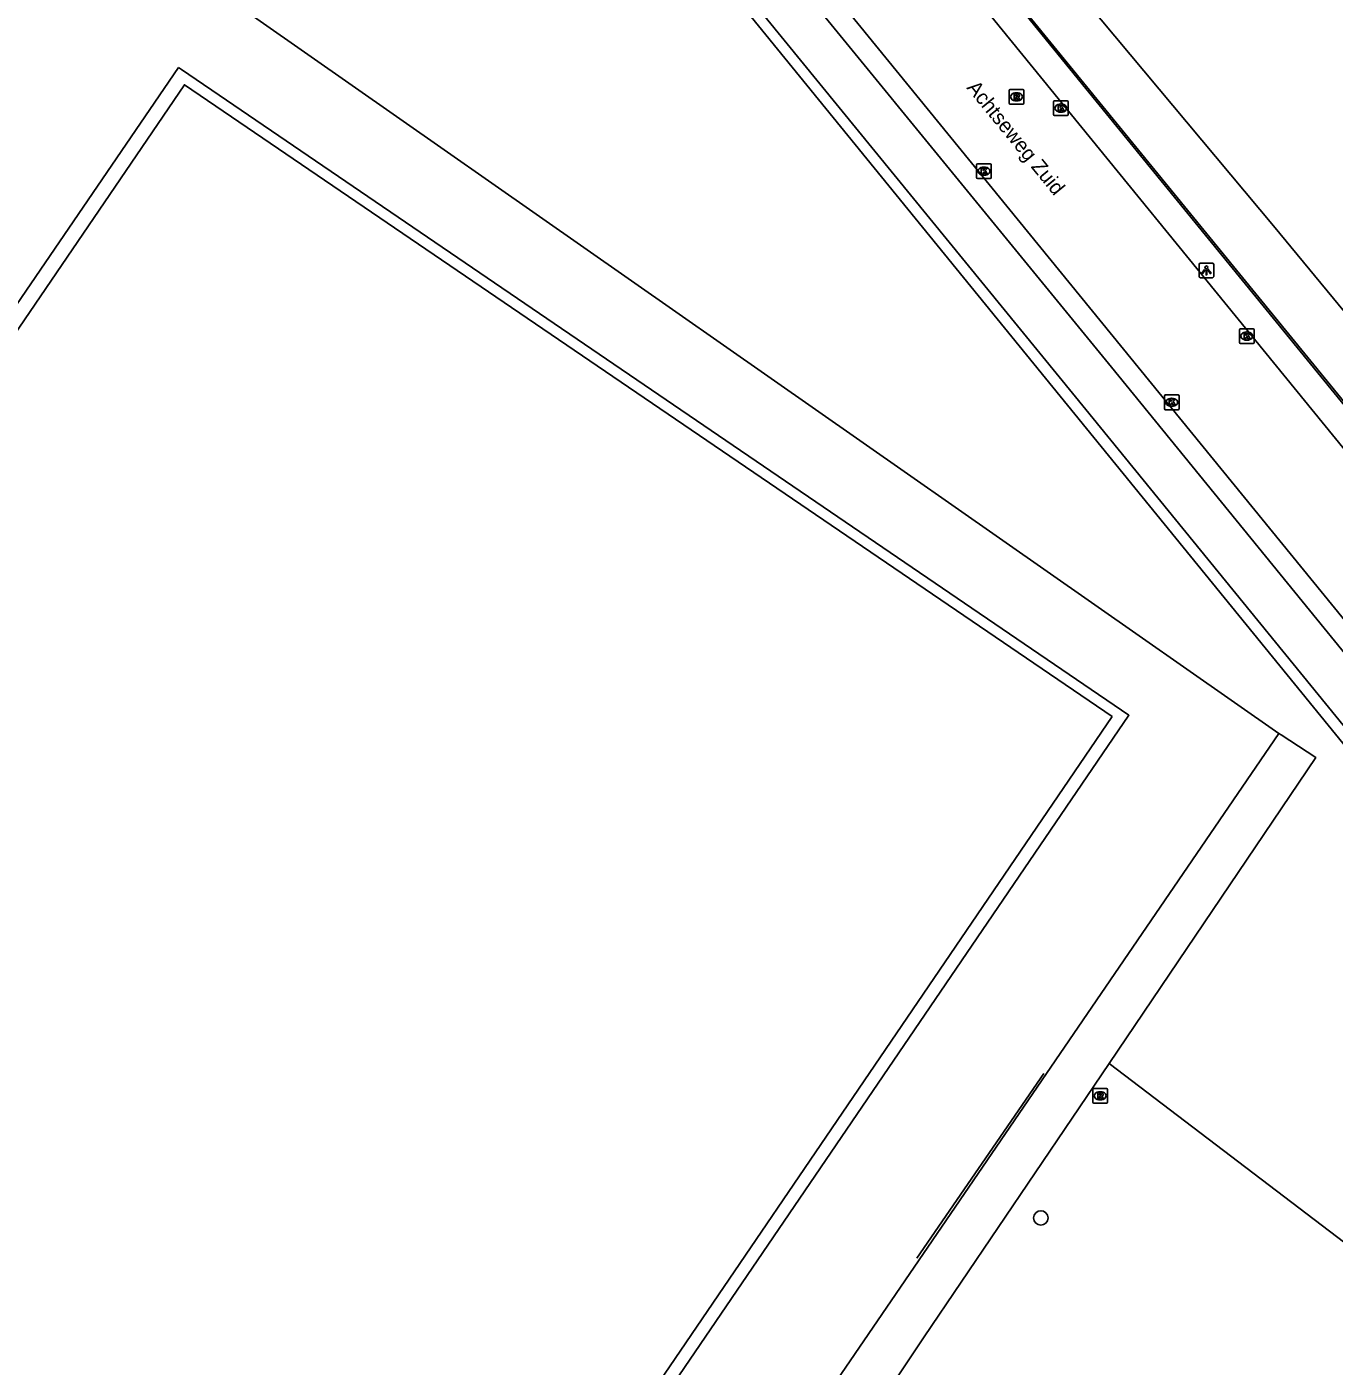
# Model space of a CAD drawing. Extents: x 157154 to 159278, y 385000 to 386650.
# Drawn here: x 158667 to 158755.9, y 385821 to 385911.9 of the extents above; entities that cross this region are included whole.
import ezdxf

# ---------------------------------------------------------------- set-up
doc = ezdxf.new("R2010")
doc.units = 0
for name, color, linetype in [('IMGEO_Berm_groen', 7, 'Continuous'), ('IMGEO_Boom', 7, 'Continuous'), ('IMGEO_Fietspad_gesloten', 7, 'Continuous'), ('IMGEO_Gemengd_bos', 7, 'Continuous'), ('IMGEO_Groenvoorziening', 7, 'Continuous'), ('IMGEO_Hek', 7, 'Continuous'), ('IMGEO_Kolk', 7, 'Continuous'), ('IMGEO_Lichtpunt', 7, 'Continuous'), ('IMGEO_Openbare_ruimte_label', 7, 'Continuous'), ('IMGEO_Rijbaan_lokaal_open', 7, 'Continuous'), ('IMGEO_Rioolput', 7, 'Continuous'), ('IMGEO_Spoorbaan_halfverhard', 7, 'Continuous'), ('IMGEO_Voetpad_open', 7, 'Continuous')]:
    doc.layers.add(name, color=color, linetype=linetype)

msp = doc.modelspace()

# ---------------------------------------------------------------- linework, layer by layer
at = {"layer": 'IMGEO_Berm_groen'}
msp.add_lwpolyline([(158841.489, 385782.337), (158835.15, 385790.114), (158809.757, 385821.269), (158676.254, 385984.739), (158663.791, 386000), (158641.091, 386027.796), (158568.335, 386116.93)], dxfattribs=at)
at = {"layer": 'IMGEO_Boom'}
msp.add_circle((158735.924, 385831.028), 0.489, dxfattribs=at)
at = {"layer": 'IMGEO_Fietspad_gesloten'}
for points in [[(158496.283, 386187.658), (158499.727, 386183.447), (158522.187, 386156.142), (158552.142, 386119.431), (158582.074, 386082.79), (158611.265, 386046.941), (158624.352, 386030.949), (158632.65, 386020.898), (158649.904, 386000), (158653.358, 385995.817), (158682.792, 385959.807), (158711.087, 385925.065), (158740.719, 385888.815), (158770.311, 385852.497), (158799.749, 385816.443), (158822.714, 385788.211), (158826.18, 385783.962)], [(158827.277, 385777.76), (158822.455, 385783.643), (158820.309, 385786.377), (158797.347, 385814.415), (158767.845, 385850.525), (158738.269, 385886.799), (158708.596, 385923.166), (158680.309, 385957.863), (158650.869, 385993.846), (158645.822, 386000), (158630.32, 386018.902), (158593.245, 386064.109), (158579.638, 386080.846), (158549.77, 386117.391), (158519.812, 386154.179), (158500, 386178.402), (158498.839, 386179.679), (158494.054, 386185.565)]]:
    msp.add_lwpolyline(points, dxfattribs=at)
at = {"layer": 'IMGEO_Gemengd_bos'}
for points in [[(158522.421, 386148.754), (158522.797, 386149.273), (158562.792, 386100.195), (158582.034, 386076.24), (158598.59, 386055.948), (158614.423, 386036.988), (158629.667, 386018.342), (158644.664, 386000), (158685.906, 385949.871), (158806.779, 385801.489), (158826.26, 385777.342), (158807.778, 385750), (158754.904, 385671.741), (158747.524, 385671.524)], [(158752.088, 385863.94), (158673.395, 385918.963), (158680.465, 385942.644), (158609.969, 386004.227), (158617.585, 386024.002), (158504.436, 386106.963), (158449.164, 386031.579), (158559.121, 385955.588)], [(158740.555, 385841.517), (158754.601, 385862.297), (158752.239, 385863.841), (158752.088, 385863.94)], [(158747.524, 385671.524), (158821.655, 385779.829), (158740.555, 385841.517)]]:
    msp.add_lwpolyline(points, dxfattribs=at)
at = {"layer": 'IMGEO_Groenvoorziening'}
for points in [[(158669.248, 385750.954), (158671.208, 385753.716), (158674.985, 385751.108), (158752.088, 385863.94)], [(158688.325, 385741.493), (158677.743, 385748.788), (158717.307, 385806.936), (158728.005, 385822.95), (158740.555, 385841.517)]]:
    msp.add_lwpolyline(points, dxfattribs=at)
at = {"layer": 'IMGEO_Hek'}
for points in [[(158817.976, 385811.106), (158808.477, 385822.704), (158800.605, 385832.374), (158792.744, 385842.021), (158789.55, 385845.893), (158757.964, 385884.486), (158738.986, 385907.741), (158732.747, 385915.407), (158728.03, 385921.204), (158723.262, 385926.998), (158694.914, 385961.78), (158690.262, 385967.581), (158687.052, 385971.435), (158669.656, 385992.715), (158661.796, 386002.376), (158660.21, 386004.291), (158633.403, 386037.186), (158611.324, 386064.219), (158568.401, 386116.979)], [(158826.26, 385777.342), (158806.779, 385801.489), (158685.906, 385949.871), (158644.664, 386000)], [(158727.505, 385828.29), (158736.135, 385840.845)]]:
    msp.add_lwpolyline(points, dxfattribs=at)
at = {"layer": 'IMGEO_Kolk'}
for p, q in [((158736.781, 385905.986), (158736.781, 385906.838)), ((158736.856, 385906.912), (158737.708, 385906.912)), ((158737.269, 385906.692), (158737.294, 385906.692)), ((158737.782, 385906.838), (158737.782, 385905.986)), ((158737.708, 385905.912), (158736.856, 385905.912)), ((158737.292, 385906.132), (158737.267, 385906.132)), ((158731.558, 385901.7), (158731.558, 385902.552)), ((158731.633, 385902.626), (158732.485, 385902.626)), ((158732.069, 385901.846), (158732.044, 385901.846)), ((158732.046, 385902.406), (158732.071, 385902.406)), ((158732.559, 385902.552), (158732.559, 385901.7)), ((158732.485, 385901.626), (158731.633, 385901.626)), ((158749.414, 385890.502), (158749.414, 385891.354)), ((158749.489, 385891.428), (158750.341, 385891.428)), ((158749.902, 385891.208), (158749.927, 385891.208)), ((158750.415, 385891.354), (158750.415, 385890.502)), ((158750.341, 385890.428), (158749.489, 385890.428)), ((158749.925, 385890.648), (158749.9, 385890.648)), ((158744.315, 385886.002), (158744.315, 385886.854)), ((158744.39, 385886.928), (158745.242, 385886.928)), ((158744.803, 385886.708), (158744.828, 385886.708)), ((158745.316, 385886.854), (158745.316, 385886.002)), ((158745.242, 385885.928), (158744.39, 385885.928)), ((158744.826, 385886.148), (158744.801, 385886.148))]:
    msp.add_line(p, q, dxfattribs=at)
for points in [[(158736.781, 385905.986), (158736.781, 385906.838)], [(158736.856, 385906.912), (158737.708, 385906.912)], [(158737.102, 385906.612), (158737.225, 385906.612), (158737.225, 385906.461), (158737.355, 385906.612), (158737.519, 385906.612), (158737.373, 385906.461), (158737.526, 385906.212), (158737.374, 385906.212), (158737.289, 385906.376), (158737.225, 385906.309), (158737.225, 385906.212), (158737.102, 385906.212), (158737.102, 385906.612)], [(158737.782, 385906.838), (158737.782, 385905.986)], [(158737.708, 385905.912), (158736.856, 385905.912)], [(158731.558, 385901.7), (158731.558, 385902.552)], [(158731.633, 385902.626), (158732.485, 385902.626)], [(158731.879, 385902.326), (158732.002, 385902.326), (158732.002, 385902.175), (158732.132, 385902.326), (158732.296, 385902.326), (158732.15, 385902.175), (158732.303, 385901.926), (158732.151, 385901.926), (158732.066, 385902.09), (158732.002, 385902.023), (158732.002, 385901.926), (158731.879, 385901.926), (158731.879, 385902.326)], [(158732.559, 385902.552), (158732.559, 385901.7)], [(158732.485, 385901.626), (158731.633, 385901.626)], [(158749.414, 385890.502), (158749.414, 385891.354)], [(158749.489, 385891.428), (158750.341, 385891.428)], [(158749.735, 385891.128), (158749.858, 385891.128), (158749.858, 385890.977), (158749.988, 385891.128), (158750.152, 385891.128), (158750.006, 385890.977), (158750.159, 385890.728), (158750.007, 385890.728), (158749.922, 385890.892), (158749.858, 385890.825), (158749.858, 385890.728), (158749.735, 385890.728), (158749.735, 385891.128)], [(158750.415, 385891.354), (158750.415, 385890.502)], [(158750.341, 385890.428), (158749.489, 385890.428)], [(158744.315, 385886.002), (158744.315, 385886.854)], [(158744.39, 385886.928), (158745.242, 385886.928)], [(158744.636, 385886.628), (158744.759, 385886.628), (158744.759, 385886.477), (158744.889, 385886.628), (158745.053, 385886.628), (158744.907, 385886.477), (158745.06, 385886.228), (158744.908, 385886.228), (158744.823, 385886.392), (158744.759, 385886.325), (158744.759, 385886.228), (158744.636, 385886.228), (158744.636, 385886.628)], [(158745.316, 385886.854), (158745.316, 385886.002)], [(158745.242, 385885.928), (158744.39, 385885.928)]]:
    msp.add_lwpolyline(points, dxfattribs=at)
for centre, start, end in [((158736.858, 385906.836), 91.55205, 178.44795), ((158736.858, 385906.836), 91.55205, 178.44795), ((158737.706, 385906.836), 1.55205, 88.44795), ((158737.706, 385906.836), 1.55205, 88.44795), ((158736.858, 385905.988), 181.55205, 268.44795), ((158736.858, 385905.988), 181.55205, 268.44795), ((158737.706, 385905.988), 271.55205, 358.44795), ((158737.706, 385905.988), 271.55205, 358.44795), ((158731.635, 385902.55), 91.55205, 178.44795), ((158731.635, 385902.55), 91.55205, 178.44795), ((158732.483, 385902.55), 1.55205, 88.44795), ((158732.483, 385902.55), 1.55205, 88.44795), ((158731.635, 385901.702), 181.55205, 268.44795), ((158731.635, 385901.702), 181.55205, 268.44795), ((158732.483, 385901.702), 271.55205, 358.44795), ((158732.483, 385901.702), 271.55205, 358.44795), ((158749.491, 385891.352), 91.55205, 178.44795), ((158749.491, 385891.352), 91.55205, 178.44795), ((158750.339, 385891.352), 1.55205, 88.44795), ((158750.339, 385891.352), 1.55205, 88.44795), ((158749.491, 385890.504), 181.55205, 268.44795), ((158749.491, 385890.504), 181.55205, 268.44795), ((158750.339, 385890.504), 271.55205, 358.44795), ((158750.339, 385890.504), 271.55205, 358.44795), ((158744.392, 385886.852), 91.55205, 178.44795), ((158744.392, 385886.852), 91.55205, 178.44795), ((158745.24, 385886.852), 1.55205, 88.44795), ((158745.24, 385886.852), 1.55205, 88.44795), ((158744.392, 385886.004), 181.55205, 268.44795), ((158744.392, 385886.004), 181.55205, 268.44795), ((158745.24, 385886.004), 271.55205, 358.44795), ((158745.24, 385886.004), 271.55205, 358.44795)]:
    msp.add_arc(centre, 0.0765, start, end, dxfattribs=at)
for centre, major_axis, ratio, start_param, end_param in [((158737.268, 385906.412), (-0.387, 0.002), 0.722429, 4.712389, 7.853982), ((158737.293, 385906.412), (-0.39, 0.002), 0.717154, 1.570796, 4.712389), ((158732.045, 385902.126), (-0.387, 0.002), 0.722429, 4.712389, 7.853982), ((158732.07, 385902.126), (-0.39, 0.002), 0.717154, 1.570796, 4.712389), ((158749.901, 385890.928), (-0.387, 0.002), 0.722429, 4.712389, 7.853982), ((158749.926, 385890.928), (-0.39, 0.002), 0.717154, 1.570796, 4.712389), ((158744.802, 385886.428), (-0.387, 0.002), 0.722429, 4.712389, 7.853982), ((158744.827, 385886.428), (-0.39, 0.002), 0.717154, 1.570796, 4.712389)]:
    msp.add_ellipse(centre, major_axis=major_axis, ratio=ratio, start_param=start_param, end_param=end_param, dxfattribs=at)
at = {"layer": 'IMGEO_Lichtpunt'}
for p, q in [((158746.672, 385895.791), (158746.672, 385894.984)), ((158746.672, 385895.791), (158746.672, 385894.984)), ((158747.574, 385895.886), (158746.766, 385895.886)), ((158747.574, 385895.886), (158746.766, 385895.886)), ((158747.668, 385894.984), (158747.668, 385895.791)), ((158747.668, 385894.984), (158747.668, 385895.791)), ((158746.766, 385894.89), (158747.574, 385894.89)), ((158746.766, 385894.89), (158747.574, 385894.89))]:
    msp.add_line(p, q, dxfattribs=at)
for points in [[(158747.046, 385895.455), (158747.085, 385895.427), (158746.897, 385895.165), (158746.859, 385895.192), (158747.046, 385895.455)], [(158747.148, 385895.407), (158747.195, 385895.407), (158747.195, 385895.085), (158747.148, 385895.085), (158747.148, 385895.407)], [(158747.258, 385895.427), (158747.296, 385895.454), (158747.483, 385895.192), (158747.444, 385895.164), (158747.258, 385895.427)]]:
    msp.add_lwpolyline(points, dxfattribs=at)
msp.add_circle((158747.171, 385895.589), 0.0994, dxfattribs=at)
for centre, start, end in [((158746.766, 385895.791), 90, 180), ((158746.766, 385895.791), 90, 180), ((158747.574, 385895.791), 0, 90), ((158747.574, 385895.791), 0, 90), ((158746.766, 385894.984), 180, 270), ((158746.766, 385894.984), 180, 270), ((158747.574, 385894.984), 270, 0), ((158747.574, 385894.984), 270, 360)]:
    msp.add_arc(centre, 0.0946, start, end, dxfattribs=at)
at = {"layer": 'IMGEO_Rijbaan_lokaal_open'}
for points in [[(158821.629, 385791.859), (158706.345, 385933.191), (158665.287, 385983.638), (158646.806, 386006.152), (158633.892, 386021.96), (158498.041, 386188.248)], [(158536.019, 386153.315), (158639.597, 386026.539), (158659.828, 386001.777), (158827.274, 385796.539)]]:
    msp.add_lwpolyline(points, dxfattribs=at)
at = {"layer": 'IMGEO_Rioolput'}
for p, q in [((158733.77, 385906.752), (158733.77, 385907.604)), ((158733.845, 385907.678), (158734.697, 385907.678)), ((158734.258, 385907.458), (158734.283, 385907.458)), ((158734.771, 385907.604), (158734.771, 385906.752)), ((158734.697, 385906.678), (158733.845, 385906.678)), ((158734.281, 385906.898), (158734.256, 385906.898)), ((158739.454, 385838.899), (158739.454, 385839.751)), ((158739.529, 385839.825), (158740.381, 385839.825)), ((158739.965, 385839.045), (158739.94, 385839.045)), ((158739.942, 385839.605), (158739.967, 385839.605)), ((158740.455, 385839.751), (158740.455, 385838.899)), ((158740.381, 385838.825), (158739.529, 385838.825))]:
    msp.add_line(p, q, dxfattribs=at)
for points in [[(158733.77, 385906.752), (158733.77, 385907.604)], [(158733.845, 385907.678), (158734.697, 385907.678)], [(158734.359, 385907.376), (158734.107, 385907.378), (158734.107, 385906.978)], [(158734.285, 385907.297), (158734.231, 385907.297), (158734.231, 385907.216)], [(158734.231, 385907.216), (158734.283, 385907.216)], [(158734.771, 385907.604), (158734.771, 385906.752)], [(158734.697, 385906.678), (158733.845, 385906.678)], [(158734.107, 385906.978), (158734.231, 385906.978), (158734.231, 385907.14), (158734.242, 385907.14)], [(158734.289, 385907.111), (158734.36, 385906.978), (158734.5, 385906.978), (158734.435, 385907.104)], [(158739.454, 385838.899), (158739.454, 385839.751)], [(158739.529, 385839.825), (158740.381, 385839.825)], [(158740.043, 385839.523), (158739.791, 385839.525), (158739.791, 385839.125)], [(158739.791, 385839.125), (158739.915, 385839.125), (158739.915, 385839.287), (158739.926, 385839.287)], [(158739.969, 385839.444), (158739.915, 385839.444), (158739.915, 385839.363)], [(158739.915, 385839.363), (158739.967, 385839.363)], [(158739.973, 385839.258), (158740.044, 385839.125), (158740.184, 385839.125), (158740.119, 385839.251)], [(158740.455, 385839.751), (158740.455, 385838.899)], [(158740.381, 385838.825), (158739.529, 385838.825)]]:
    msp.add_lwpolyline(points, dxfattribs=at)
for centre, radius, start, end in [((158733.847, 385907.602), 0.0765, 91.55205, 178.44795), ((158733.847, 385907.602), 0.0765, 91.55205, 178.44795), ((158734.267, 385907.405), 0.19, 274.7715, 282.96867), ((158734.291, 385907.201), 0.0964, 77.00612, 93.18647), ((158734.305, 385907.258), 0.0378, 276.66336, 79.67722), ((158734.358, 385907.266), 0.109, 350.36119, 89.41601), ((158734.356, 385907.266), 0.112, 277.58423, 350.98172), ((158734.695, 385907.602), 0.0765, 1.55205, 88.44795), ((158734.695, 385907.602), 0.0765, 1.55205, 88.44795), ((158733.847, 385906.754), 0.0765, 181.55205, 268.44795), ((158733.847, 385906.754), 0.0765, 181.55205, 268.44795), ((158734.241, 385907.087), 0.0533, 26.02933, 88.69889), ((158734.34, 385907.051), 0.108, 29.51342, 73.79051), ((158734.695, 385906.754), 0.0765, 271.55205, 358.44795), ((158734.695, 385906.754), 0.0765, 271.55205, 358.44795), ((158739.531, 385839.749), 0.0765, 91.55205, 178.44795), ((158739.531, 385839.749), 0.0765, 91.55205, 178.44795), ((158739.925, 385839.234), 0.0533, 26.02933, 88.69889), ((158739.951, 385839.552), 0.19, 274.7715, 282.96867), ((158739.975, 385839.348), 0.0964, 77.00612, 93.18647), ((158739.989, 385839.405), 0.0378, 276.66336, 79.67722), ((158740.042, 385839.413), 0.109, 350.36119, 89.41601), ((158740.04, 385839.413), 0.112, 277.58423, 350.98172), ((158740.024, 385839.198), 0.108, 29.51342, 73.79051), ((158740.379, 385839.749), 0.0765, 1.55205, 88.44795), ((158740.379, 385839.749), 0.0765, 1.55205, 88.44795), ((158739.531, 385838.901), 0.0765, 181.55205, 268.44795), ((158739.531, 385838.901), 0.0765, 181.55205, 268.44795), ((158740.379, 385838.901), 0.0765, 271.55205, 358.44795), ((158740.379, 385838.901), 0.0765, 271.55205, 358.44795)]:
    msp.add_arc(centre, radius, start, end, dxfattribs=at)
for centre, major_axis, ratio, start_param, end_param in [((158734.257, 385907.178), (-0.387, 0.002), 0.722429, 4.712389, 7.853982), ((158734.282, 385907.178), (-0.39, 0.002), 0.717154, 1.570796, 4.712389), ((158739.941, 385839.325), (-0.387, 0.002), 0.722429, 4.712389, 7.853982), ((158739.966, 385839.325), (-0.39, 0.002), 0.717154, 1.570796, 4.712389)]:
    msp.add_ellipse(centre, major_axis=major_axis, ratio=ratio, start_param=start_param, end_param=end_param, dxfattribs=at)
at = {"layer": 'IMGEO_Spoorbaan_halfverhard'}
msp.add_lwpolyline([(158539.004, 386155.645), (158551.223, 386140.801), (158563.891, 386125.785), (158579.038, 386107.589), (158585.995, 386098.767), (158593.705, 386089.591), (158604.841, 386075.981), (158612.287, 386067.119), (158630.237, 386045.448), (158637.03, 386036.964), (158663.463, 386005.216), (158671.744, 385994.913), (158680.709, 385984.692), (158688.421, 385975.364), (158694.021, 385968.581), (158700.961, 385959.859), (158733.183, 385920.595), (158751.735, 385898.407), (158775.523, 385869.582), (158795.823, 385845.315), (158809.961, 385828.171), (158813.558, 385823.456), (158818.967, 385817.08), (158842.26, 385789.002)], dxfattribs=at)
at = {"layer": 'IMGEO_Voetpad_open'}
for points in [[(158677.333, 385909.177), (158677.545, 385909.039), (158741.912, 385865.17), (158677.268, 385770.319), (158612.929, 385814.152), (158612.605, 385814.369), (158677.333, 385909.177)], [(158740.773, 385865.078), (158677.742, 385908.001), (158613.968, 385814.349), (158676.999, 385771.427), (158740.773, 385865.078)]]:
    msp.add_lwpolyline(points, dxfattribs=at)

# ---------------------------------------------------------------- texts
at = {"layer": 'IMGEO_Openbare_ruimte_label'}
msp.add_text('Achtseweg Zuid', height=1, rotation=309.19669, dxfattribs=at).set_placement((158730.842, 385907.777))

doc.saveas('drawing.dxf')
